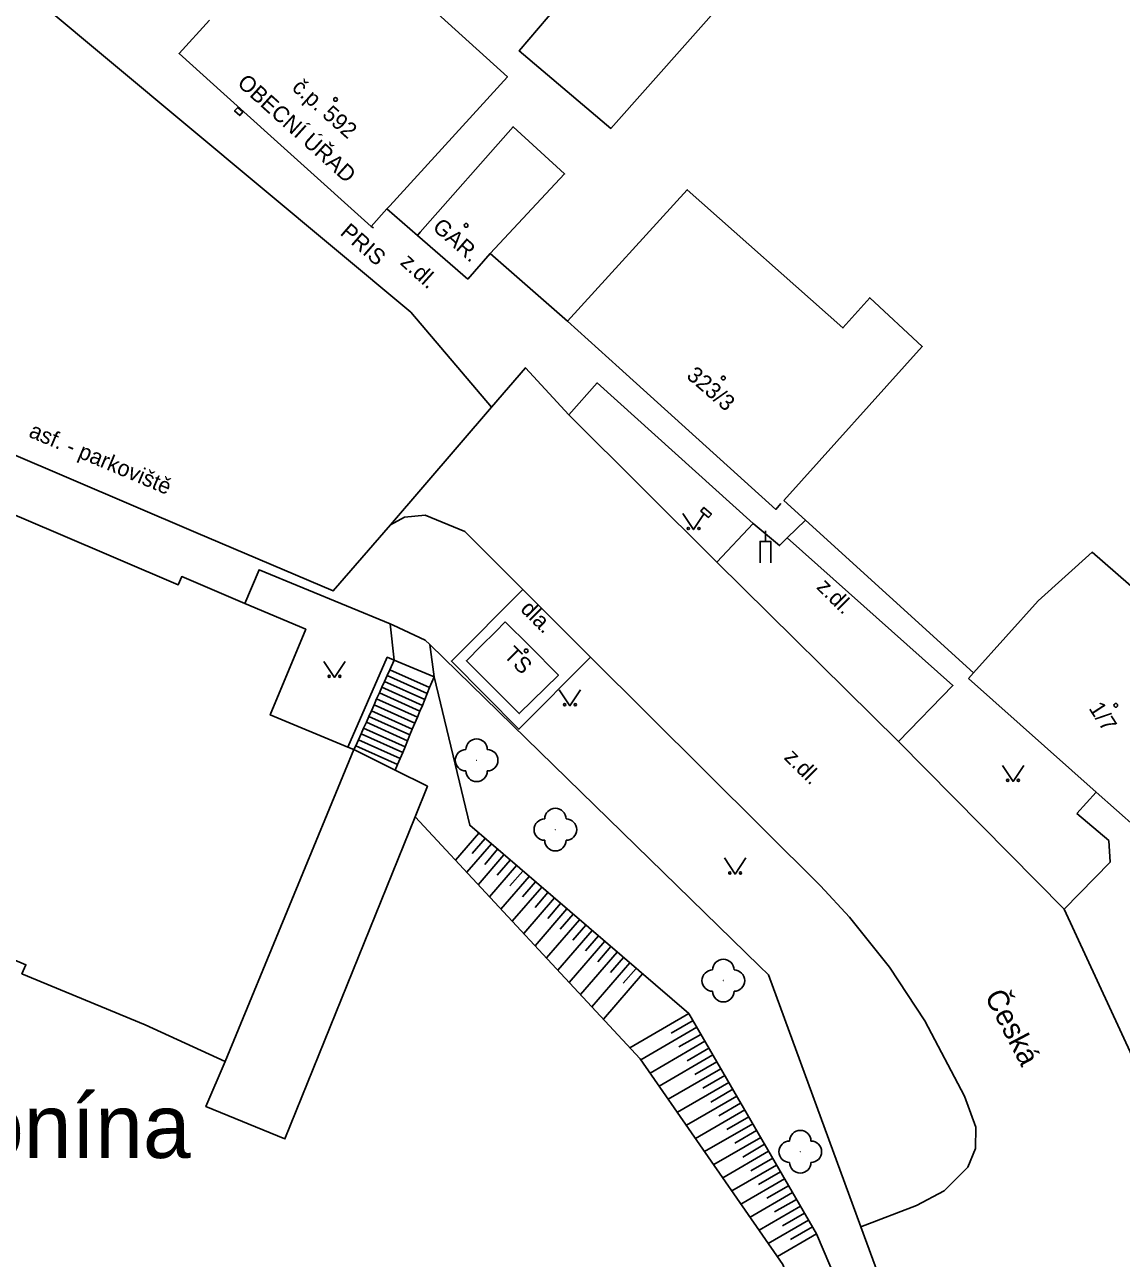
# Model space of a CAD drawing. Extents: x -577457 to -568404, y -1208466 to -1201387.
# Drawn here: x -568784.4 to -568733.1, y -1204034 to -1203976.2 of the extents above; entities that cross this region are included whole.
import ezdxf

# ---------------------------------------------------------------- set-up
doc = ezdxf.new("R2010")
doc.units = 0
for name, color, linetype in [('BUDOVY_MĚŘ', 7, 'Continuous'), ('BUDOVY_NEMĚŘ', 7, 'Continuous'), ('NÁZEV_K_Ú', 7, 'Continuous'), ('NÁZVY_ULIC_TOK_SMĚR', 7, 'Continuous'), ('OBVOD_PILÍŘE', 7, 'Continuous'), ('POMOC_POPIS', 7, 'Continuous'), ('ROZHRANÍ_PLOCH', 7, 'Continuous'), ('VÝŠKOPIS', 7, 'Continuous'), ('ZELEŇ', 7, 'Continuous'), ('ZN_BUDOV', 7, 'Continuous'), ('ZN_DOPLŇKOVÉ', 7, 'Continuous'), ('ZN_KULTUR', 7, 'Continuous'), ('Č_POPIS_ORIENT', 7, 'Continuous')]:
    doc.layers.add(name, color=color, linetype=linetype)

msp = doc.modelspace()

# ---------------------------------------------------------------- linework, layer by layer
at = {"layer": 'BUDOVY_MĚŘ'}
for points in [[(-568775.76, -1203976), (-568777.18, -1203977.56), (-568775.08, -1203979.45)], [(-568775.08, -1203979.45), (-568768.19, -1203985.66)], [(-568768.19, -1203985.66), (-568767.45, -1203984.84)], [(-568767.45, -1203984.84), (-568767.31, -1203984.69)], [(-568765.89, -1203985.93), (-568766.02, -1203986.08)], [(-568766.02, -1203986.08), (-568763.66, -1203988.13)], [(-568763.66, -1203988.13), (-568762.62, -1203986.93)], [(-568758.99, -1203990.09), (-568756.57, -1203992.28)], [(-568756.57, -1203992.28), (-568749.25, -1203998.91), (-568749.01, -1203998.64)], [(-568782.94, -1204000), (-568791.78, -1203996.23), (-568791.54, -1203995.67)], [(-568774.1, -1204003.32), (-568777.05, -1204002.06), (-568777.22, -1204002.45), (-568782.94, -1204000)], [(-568769.27, -1204010.05), (-568772.91, -1204008.54), (-568771.25, -1204004.53), (-568774.1, -1204003.32)], [(-568761.91, -1204004.18), (-568760.78, -1204005.31), (-568759.42, -1204006.67), (-568761.25, -1204008.48), (-568763.24, -1204006.49), (-568763.73, -1204006), (-568763.03, -1204005.3), (-568762.37, -1204004.64), (-568761.91, -1204004.18)], [(-568739.99, -1204006.56), (-568740.23, -1204006.83)], [(-568740.23, -1204006.83), (-568734.25, -1204012.15)], [(-568775.02, -1204024.77), (-568768.99, -1204010.16)], [(-568768.99, -1204010.16), (-568769.27, -1204010.05)], [(-568734.25, -1204012.15), (-568732.34, -1204013.85), (-568732.27, -1204013.78)]]:
    msp.add_lwpolyline(points, dxfattribs=at)
at = {"layer": 'BUDOVY_NEMĚŘ'}
for points in [[(-568762.24, -1203958.28), (-568760.87, -1203959.38), (-568759.05, -1203957.28), (-568754.74, -1203960.91), (-568756.56, -1203963.12), (-568747.81, -1203970.74), (-568756.96, -1203981.07), (-568761.25, -1203977.44), (-568758.54, -1203974.24), (-568764.53, -1203968.73)], [(-568770.79, -1203970.5), (-568761.81, -1203978.66), (-568767.31, -1203984.69)], [(-568762.62, -1203986.93), (-568759.13, -1203983.2), (-568761.54, -1203980.99), (-568765.89, -1203985.93)], [(-568758.99, -1203990.09), (-568753.39, -1203983.94), (-568746.1, -1203990.41), (-568744.85, -1203989), (-568742.39, -1203991.29), (-568748.87, -1203998.49)], [(-568739.99, -1204006.56), (-568736.96, -1204003.2), (-568734.43, -1204000.92), (-568730.42, -1204004.41), (-568729.39, -1204003.25), (-568725.71, -1204006.54), (-568730.81, -1204012.11), (-568732.27, -1204013.78)], [(-568807.5, -1204010.83), (-568799.35, -1204014.36), (-568799.12, -1204013.97), (-568784.35, -1204020.24), (-568784.53, -1204020.66), (-568778.77, -1204023.06), (-568775.02, -1204024.77)]]:
    msp.add_lwpolyline(points, dxfattribs=at)
at = {"layer": 'OBVOD_PILÍŘE'}
for points in [[(-568774.46, -1203980.36), (-568774.58, -1203980.25), (-568774.43, -1203980.09), (-568774.19, -1203980.3), (-568774.34, -1203980.47), (-568774.46, -1203980.36)], [(-568752.58, -1203999.14), (-568752.76, -1203998.99), (-568752.61, -1203998.82), (-568752.26, -1203999.13), (-568752.4, -1203999.29), (-568752.58, -1203999.14)]]:
    msp.add_lwpolyline(points, dxfattribs=at)
at = {"layer": 'ROZHRANÍ_PLOCH'}
for points in [[(-568766.33, -1203989.68), (-568790.8, -1203969.25)], [(-568768.19, -1203985.66), (-568768.07, -1203985.73)], [(-568762.56, -1203994.13), (-568766.33, -1203989.68)], [(-568758.94, -1203994.48), (-568760.96, -1203992.28), (-568762.56, -1203994.13)], [(-568758.94, -1203994.48), (-568757.6, -1203992.99), (-568750.3, -1203999.57)], [(-568767.28, -1203999.64), (-568762.56, -1203994.13)], [(-568752, -1204001.38), (-568758.94, -1203994.48)], [(-568776.39, -1204000), (-568788.19, -1203994.95)], [(-568767.28, -1203999.64), (-568766.63, -1203999.28), (-568765.66, -1203999.19), (-568763.8, -1203999.95), (-568761.08, -1204002.67)], [(-568748.72, -1204000.24), (-568747.85, -1203999.41)], [(-568767.28, -1203999.64), (-568769.96, -1204002.73), (-568776.39, -1204000)], [(-568750.3, -1203999.57), (-568752, -1204001.38)], [(-568750.3, -1203999.57), (-568749.07, -1204000.61), (-568748.72, -1204000.24)], [(-568748.72, -1204000.24), (-568740.95, -1204007.16), (-568743.5, -1204009.79)], [(-568752, -1204001.38), (-568743.5, -1204009.79)], [(-568761.08, -1204002.67), (-568764.43, -1204006.02), (-568761.27, -1204009.21), (-568757.92, -1204005.84)], [(-568761.08, -1204002.67), (-568757.92, -1204005.84)], [(-568767.29, -1204004.27), (-568767.11, -1204005.98)], [(-568765.44, -1204005.24), (-568765.24, -1204006.76)], [(-568767.11, -1204005.98), (-568767.43, -1204005.84), (-568769.27, -1204010.05)], [(-568767.31, -1204006.42), (-568767.11, -1204005.98)], [(-568767.11, -1204005.98), (-568765.24, -1204006.76)], [(-568757.92, -1204005.84), (-568747.15, -1204016.54), (-568745.8, -1204018.01), (-568743.92, -1204020.36), (-568742.27, -1204022.86), (-568740.41, -1204026.4), (-568739.88, -1204027.84), (-568739.9, -1204028.84), (-568740.26, -1204029.72), (-568741.36, -1204030.83), (-568742.66, -1204031.52), (-568745.26, -1204032.52)], [(-568767.56, -1204006.97), (-568767.43, -1204006.69)], [(-568767.43, -1204006.69), (-568767.31, -1204006.42)], [(-568765.56, -1204007.53), (-568767.43, -1204006.69)], [(-568765.45, -1204007.26), (-568767.31, -1204006.42)], [(-568765.45, -1204007.26), (-568765.24, -1204006.76)], [(-568767.8, -1204007.51), (-568767.68, -1204007.24)], [(-568767.68, -1204007.24), (-568767.56, -1204006.97)], [(-568765.79, -1204008.09), (-568767.68, -1204007.24)], [(-568765.68, -1204007.81), (-568767.56, -1204006.97)], [(-568765.56, -1204007.53), (-568765.45, -1204007.26)], [(-568768.17, -1204008.34), (-568768.05, -1204008.06)], [(-568768.05, -1204008.06), (-568767.93, -1204007.79)], [(-568766.14, -1204008.92), (-568768.05, -1204008.06)], [(-568767.93, -1204007.79), (-568767.8, -1204007.51)], [(-568766.02, -1204008.64), (-568767.93, -1204007.79)], [(-568765.9, -1204008.36), (-568767.8, -1204007.51)], [(-568765.79, -1204008.09), (-568765.68, -1204007.81)], [(-568765.68, -1204007.81), (-568765.56, -1204007.53)], [(-568768.41, -1204008.88), (-568768.29, -1204008.61)], [(-568768.29, -1204008.61), (-568768.17, -1204008.34)], [(-568766.37, -1204009.47), (-568768.29, -1204008.61)], [(-568766.26, -1204009.2), (-568768.17, -1204008.34)], [(-568766.14, -1204008.92), (-568766.02, -1204008.64)], [(-568766.02, -1204008.64), (-568765.9, -1204008.36)], [(-568765.9, -1204008.36), (-568765.79, -1204008.09)], [(-568768.66, -1204009.43), (-568768.54, -1204009.16)], [(-568768.54, -1204009.16), (-568768.41, -1204008.88)], [(-568766.6, -1204010.03), (-568768.54, -1204009.16)], [(-568766.49, -1204009.75), (-568768.41, -1204008.88)], [(-568766.37, -1204009.47), (-568766.26, -1204009.2)], [(-568766.26, -1204009.2), (-568766.14, -1204008.92)], [(-568768.91, -1204009.98), (-568768.78, -1204009.7)], [(-568768.78, -1204009.7), (-568768.66, -1204009.43)], [(-568766.83, -1204010.58), (-568768.78, -1204009.7)], [(-568766.71, -1204010.3), (-568768.66, -1204009.43)], [(-568766.6, -1204010.03), (-568766.49, -1204009.75)], [(-568766.49, -1204009.75), (-568766.37, -1204009.47)], [(-568743.5, -1204009.79), (-568735.75, -1204017.64)], [(-568768.99, -1204010.16), (-568768.91, -1204009.98)], [(-568767.06, -1204011.12), (-568768.99, -1204010.16)], [(-568766.95, -1204010.86), (-568768.91, -1204009.98)], [(-568766.83, -1204010.58), (-568766.71, -1204010.3)], [(-568766.71, -1204010.3), (-568766.6, -1204010.03)], [(-568767.06, -1204011.12), (-568766.95, -1204010.86)], [(-568766.95, -1204010.86), (-568766.83, -1204010.58)], [(-568775.02, -1204024.77), (-568775.92, -1204026.88), (-568772.22, -1204028.4), (-568766.13, -1204013.31), (-568765.55, -1204011.88), (-568767.06, -1204011.12)], [(-568734.25, -1204012.15), (-568735.16, -1204013.16)], [(-568733.65, -1204014.42), (-568735.16, -1204013.16)], [(-568733.6, -1204015.44), (-568733.65, -1204014.42)], [(-568735.75, -1204017.64), (-568733.6, -1204015.44)], [(-568735.75, -1204017.64), (-568732.56, -1204024.52)]]:
    msp.add_lwpolyline(points, dxfattribs=at)
at = {"layer": 'VÝŠKOPIS'}
for points in [[(-568750, -1204032.71), (-568755.59, -1204024.64), (-568766.13, -1204013.31)], [(-568763.15, -1204014.07), (-568764.24, -1204015.34)], [(-568762.85, -1204014.33), (-568763.46, -1204015.03)], [(-568762.56, -1204014.58), (-568763.71, -1204015.91)], [(-568762.27, -1204014.83), (-568762.87, -1204015.54)], [(-568761.97, -1204015.09), (-568763.17, -1204016.49)], [(-568761.38, -1204015.59), (-568762.64, -1204017.06)], [(-568761.68, -1204015.34), (-568762.28, -1204016.04)], [(-568760.79, -1204016.1), (-568762.11, -1204017.63)], [(-568761.09, -1204015.85), (-568761.69, -1204016.55)], [(-568760.2, -1204016.61), (-568761.58, -1204018.2)], [(-568760.5, -1204016.35), (-568761.1, -1204017.06)], [(-568759.61, -1204017.11), (-568761.04, -1204018.78)], [(-568759.91, -1204016.86), (-568760.51, -1204017.56)], [(-568759.02, -1204017.62), (-568760.51, -1204019.35)], [(-568759.32, -1204017.37), (-568759.92, -1204018.07)], [(-568758.73, -1204017.87), (-568759.34, -1204018.58)], [(-568758.43, -1204018.13), (-568759.98, -1204019.92)], [(-568758.14, -1204018.38), (-568758.75, -1204019.09)], [(-568757.84, -1204018.63), (-568759.44, -1204020.5)], [(-568757.55, -1204018.89), (-568758.16, -1204019.59)], [(-568757.25, -1204019.14), (-568758.91, -1204021.07)], [(-568756.96, -1204019.39), (-568757.57, -1204020.1)], [(-568756.67, -1204019.65), (-568758.38, -1204021.64)], [(-568756.07, -1204020.15), (-568757.85, -1204022.21)], [(-568756.37, -1204019.9), (-568756.98, -1204020.61)], [(-568755.49, -1204020.66), (-568757.31, -1204022.79)], [(-568755.78, -1204020.41), (-568756.39, -1204021.11)], [(-568753.31, -1204022.53), (-568756.07, -1204024.13)], [(-568753.12, -1204022.85), (-568754.15, -1204023.45)], [(-568752.94, -1204023.17), (-568755.56, -1204024.69)], [(-568752.75, -1204023.5), (-568753.78, -1204024.09)], [(-568752.56, -1204023.82), (-568755.13, -1204025.31)], [(-568752.38, -1204024.14), (-568753.4, -1204024.74)], [(-568752.19, -1204024.46), (-568754.7, -1204025.92)], [(-568752, -1204024.78), (-568753.03, -1204025.38)], [(-568751.82, -1204025.11), (-568754.28, -1204026.53)], [(-568751.44, -1204025.75), (-568753.85, -1204027.15)], [(-568751.63, -1204025.43), (-568752.66, -1204026.02)], [(-568751.07, -1204026.4), (-568753.43, -1204027.76)], [(-568751.26, -1204026.07), (-568752.28, -1204026.67)], [(-568750.7, -1204027.04), (-568753, -1204028.38)], [(-568750.89, -1204026.72), (-568751.91, -1204027.31)], [(-568750.32, -1204027.69), (-568752.58, -1204028.99)], [(-568750.51, -1204027.36), (-568751.54, -1204027.96)], [(-568750.14, -1204028.01), (-568751.16, -1204028.6)], [(-568749.95, -1204028.33), (-568752.15, -1204029.6)], [(-568749.77, -1204028.65), (-568750.79, -1204029.25)], [(-568749.58, -1204028.97), (-568751.73, -1204030.22)], [(-568749.39, -1204029.3), (-568750.42, -1204029.89)], [(-568749.21, -1204029.62), (-568751.3, -1204030.83)], [(-568749.02, -1204029.94), (-568750.05, -1204030.53)], [(-568748.83, -1204030.26), (-568750.88, -1204031.45)], [(-568748.65, -1204030.59), (-568749.67, -1204031.18)], [(-568748.46, -1204030.91), (-568750.45, -1204032.06)], [(-568748.09, -1204031.55), (-568750.02, -1204032.67)], [(-568748.27, -1204031.23), (-568749.3, -1204031.82)], [(-568747.71, -1204032.2), (-568749.6, -1204033.29)], [(-568747.9, -1204031.87), (-568748.93, -1204032.47)], [(-568750, -1204073.36), (-568746.5, -1204068.86), (-568740.04, -1204056.66), (-568741.39, -1204052.86), (-568748.91, -1204034.28), (-568750, -1204032.71)], [(-568747.34, -1204032.84), (-568749.17, -1204033.9)], [(-568747.53, -1204032.52), (-568748.55, -1204033.11)]]:
    msp.add_lwpolyline(points, dxfattribs=at)
at = {"layer": 'ZELEŇ'}
for centre in [(-568763.25, -1204010.66), (-568759.56, -1204013.91), (-568751.7, -1204020.98), (-568748.1, -1204029)]:
    msp.add_circle(centre, 0.0005, dxfattribs=at)
for centre, start, end in [((-568763.25, -1204010.16), 0, 179.99999), ((-568763.75, -1204010.66), 89.99999, 269.99999), ((-568762.75, -1204010.66), 270, 89.99999), ((-568763.25, -1204011.16), 179.99999, 359.99999), ((-568759.56, -1204013.41), 0, 179.99999), ((-568760.06, -1204013.91), 89.99999, 269.99999), ((-568759.06, -1204013.91), 270, 89.99999), ((-568759.56, -1204014.41), 179.99999, 359.99999), ((-568751.7, -1204020.48), 0, 179.99999), ((-568752.2, -1204020.98), 89.99999, 269.99999), ((-568751.2, -1204020.98), 270, 89.99999), ((-568751.7, -1204021.48), 179.99999, 359.99999), ((-568748.1, -1204028.5), 0, 179.99999), ((-568748.6, -1204029), 89.99999, 269.99999), ((-568747.6, -1204029), 270, 89.99999), ((-568748.1, -1204029.5), 179.99999, 359.99999)]:
    msp.add_arc(centre, 0.5, start, end, dxfattribs=at)
at = {"layer": 'ZN_BUDOV'}
for centre in [(-568769.85, -1203979.71), (-568763.74, -1203985.61), (-568751.7, -1203992.76), (-568760.93, -1204005.54), (-568733.33, -1204008.09)]:
    msp.add_circle(centre, 0.0875, dxfattribs=at)
at = {"layer": 'ZN_DOPLŇKOVÉ'}
msp.add_line((-568749.73, -1204000.41), (-568749.73, -1203999.91), dxfattribs=at)
for points in [[(-568767.45, -1203984.84), (-568766.02, -1203986.08)], [(-568762.62, -1203986.93), (-568758.99, -1203990.09)], [(-568747.85, -1203999.41), (-568748.87, -1203998.49)], [(-568747.85, -1203999.41), (-568739.99, -1204006.56)], [(-568749.98, -1204001.41), (-568749.98, -1204000.41), (-568749.48, -1204000.41), (-568749.48, -1204001.41)], [(-568767.29, -1204004.27), (-568773.43, -1204001.74), (-568774.1, -1204003.32)], [(-568767.29, -1204004.27), (-568767.15, -1204004.33)], [(-568765.65, -1204005.03), (-568767.15, -1204004.33)], [(-568765.65, -1204005.03), (-568765.44, -1204005.24)], [(-568750, -1204020.31), (-568765.44, -1204005.24)], [(-568765.24, -1204006.76), (-568763.57, -1204013.71), (-568753.31, -1204022.53)], [(-568745.26, -1204032.52), (-568749.59, -1204020.71), (-568750, -1204020.31)], [(-568753.31, -1204022.53), (-568747.34, -1204032.84)], [(-568747.34, -1204032.84), (-568739.54, -1204051.19), (-568737.33, -1204055.64), (-568744.54, -1204068.79)], [(-568743.58, -1204037.11), (-568745.26, -1204032.52)]]:
    msp.add_lwpolyline(points, dxfattribs=at)
at = {"layer": 'ZN_KULTUR'}
for points in [[(-568753.59, -1203999.11), (-568753.09, -1203999.86), (-568752.59, -1203999.11)], [(-568770.4, -1204006.03), (-568769.9, -1204006.78), (-568769.4, -1204006.03)], [(-568759.38, -1204007.36), (-568758.88, -1204008.11), (-568758.38, -1204007.36)], [(-568738.64, -1204010.9), (-568738.14, -1204011.65), (-568737.64, -1204010.9)], [(-568751.65, -1204015.24), (-568751.15, -1204015.99), (-568750.65, -1204015.24)]]:
    msp.add_lwpolyline(points, dxfattribs=at)
for centre in [(-568753.34, -1203999.81), (-568752.84, -1203999.81), (-568770.15, -1204006.73), (-568769.65, -1204006.73), (-568759.13, -1204008.06), (-568758.63, -1204008.06), (-568738.39, -1204011.6), (-568737.89, -1204011.6), (-568751.4, -1204015.94), (-568750.9, -1204015.94)]:
    msp.add_circle(centre, 0.05, dxfattribs=at)

# ---------------------------------------------------------------- texts
at = {"layer": 'NÁZEV_K_Ú'}
msp.add_text('k.ú.Lužice u Hodonína', height=3, dxfattribs=at).set_placement((-568816.56, -1204029.29))
at = {"layer": 'NÁZVY_ULIC_TOK_SMĚR'}
msp.add_text('Česká', height=1, rotation=297.7185, dxfattribs=at).set_placement((-568739.49, -1204021.71))
at = {"layer": 'POMOC_POPIS'}
for s, rotation, p in [('OBECNÍ ÚŘAD', 317.98, (-568774.5, -1203979.01)), ('PRIS', 318.99001, (-568769.68, -1203986.01)), ('GAR.', 318.99001, (-568765.36, -1203985.77)), ('z.dl.', 317.85619, (-568766.87, -1203987.4)), ('asf. - parkoviště', 337.19941, (-568784.26, -1203995.5)), ('z.dl.', 315.30492, (-568747.38, -1204002.59)), ('dla.', 314.90946, (-568761.24, -1204003.63)), ('TS', 314.99999, (-568762.02, -1204005.78)), ('z.dl.', 315.18678, (-568748.9, -1204010.57))]:
    msp.add_text(s, height=0.75, rotation=rotation, dxfattribs=at).set_placement(p)
at = {"layer": 'Č_POPIS_ORIENT'}
for s, rotation, p in [('č.p. 592', 318.47, (-568771.94, -1203979.23)), ('323/3', 319.27999, (-568753.47, -1203992.72)), ('1/7', 303.08001, (-568734.62, -1204008.23))]:
    msp.add_text(s, height=0.75, rotation=rotation, dxfattribs=at).set_placement(p)

doc.saveas('drawing.dxf')
